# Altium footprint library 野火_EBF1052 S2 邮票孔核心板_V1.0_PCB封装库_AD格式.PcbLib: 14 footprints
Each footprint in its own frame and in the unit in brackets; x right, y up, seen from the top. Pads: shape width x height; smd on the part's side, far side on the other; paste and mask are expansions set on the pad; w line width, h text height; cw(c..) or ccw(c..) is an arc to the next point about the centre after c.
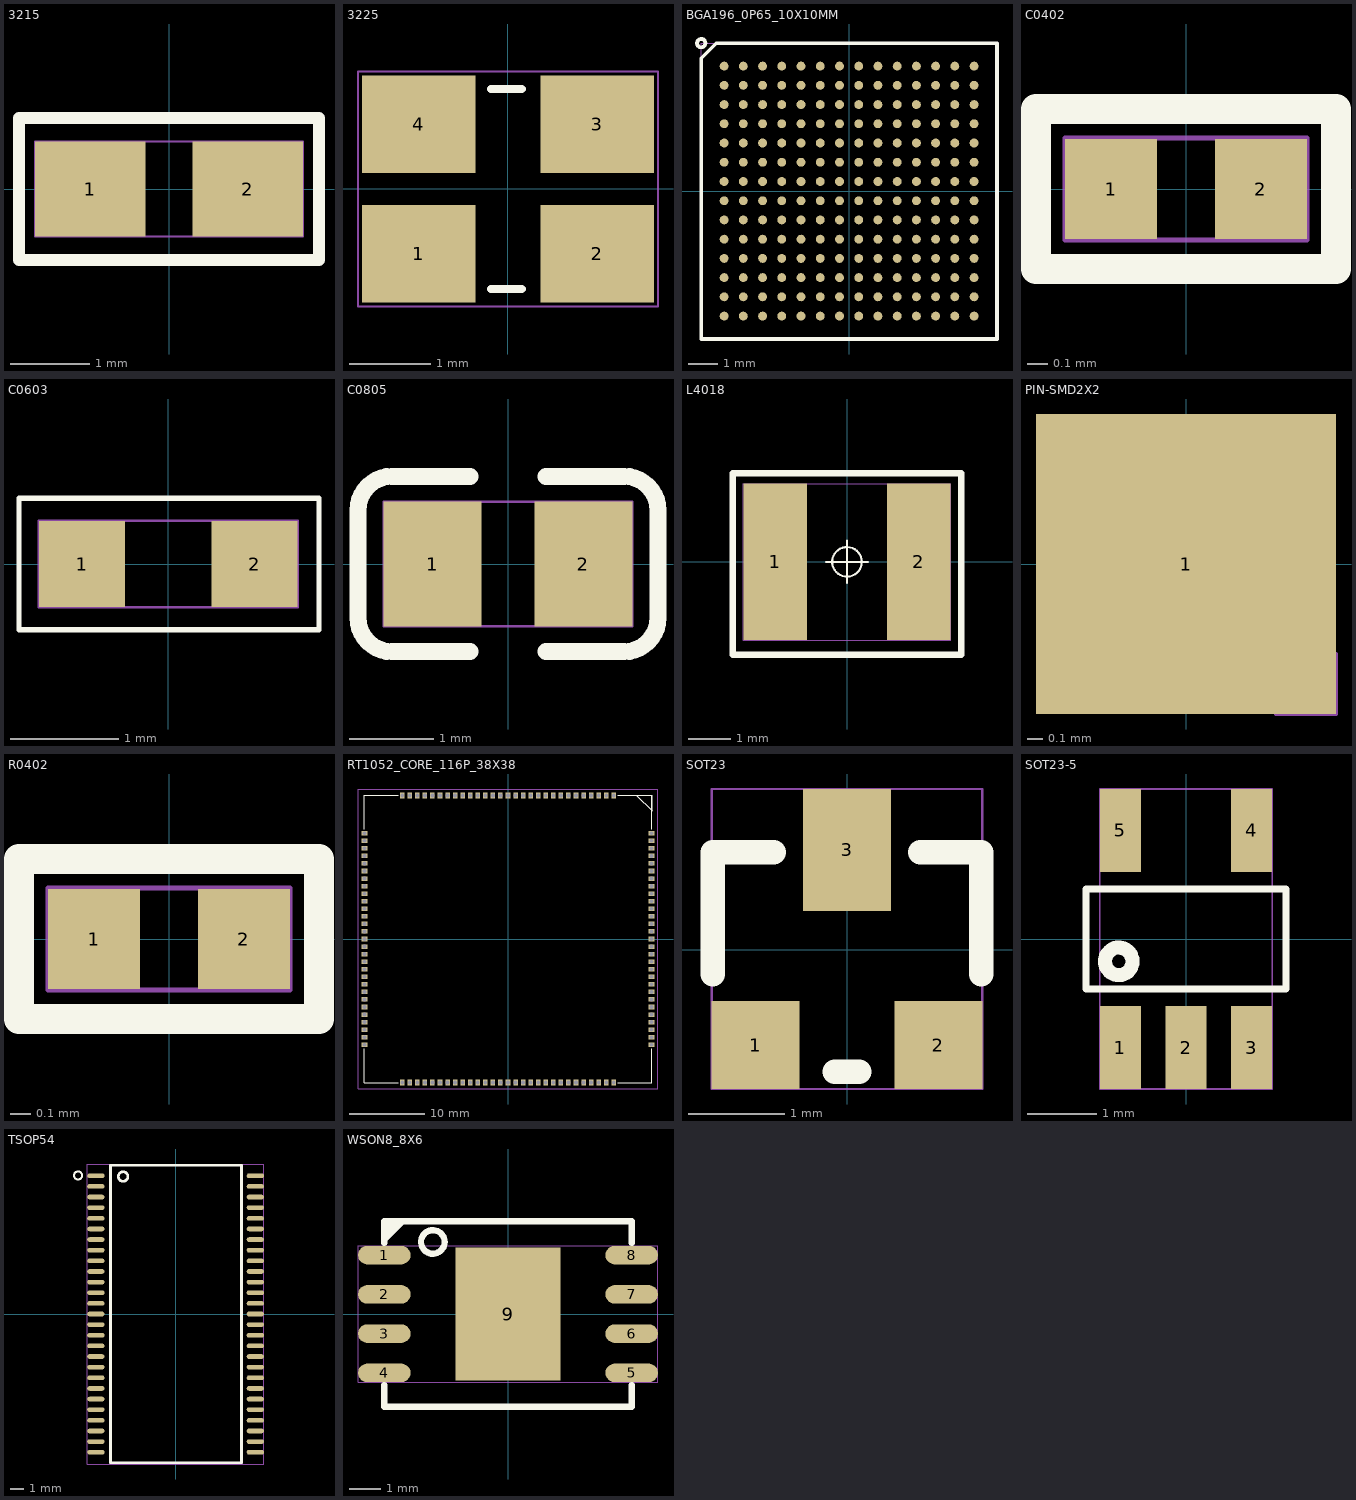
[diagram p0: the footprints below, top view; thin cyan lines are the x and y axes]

## 3215 [mm]
pads (2):
  rect 1.4x1.2 smd mask+0.05: 1(-1,0) 2(1,0)
Top Overlay:
  lines w0.15: -1.9,-0.9 1.9,-0.9 1.9,0.9 -1.9,0.9 -1.9,-0.9
Top Assembly:
  text "Y2" at -0.989,-0.635 h1.27
Mechanical 16:
  lines w0.025: -1.7,-0.6 -1.7,0.6 1.7,0.6 1.7,-0.6 -1.7,-0.6

## 3225 [mil]
pads (4):
  rect 55.12x47.24 smd mask+1.97: 1(-43.3,-31.5) 2(43.31,-31.5) 3(43.31,31.49) 4(-43.3,31.49)
Top Overlay:
  lines w3.94: -8.3,-48.51 6.7,-48.51 ; -8.3,48.51 6.7,48.51
Top Assembly:
  text "Y1" at 28.21,25 h50
Mechanical 16:
  lines w1: -72.83,-57.09 72.84,-57.09 72.84,57.08 -72.83,57.08 -72.83,-57.09

## BGA196_0P65_10X10MM [mm]
pads (196):
  round 0.3 smd mask+0.05: A1(-4.225,4.225) A2(-3.575,4.225) A3(-2.925,4.225) A4(-2.275,4.225) A5(-1.625,4.225) A6(-0.975,4.225) A7(-0.325,4.225) A8(0.325,4.225) A9(0.975,4.225) A10(1.625,4.225) A11(2.275,4.225) A12(2.925,4.225) A13(3.575,4.225) A14(4.225,4.225) B1(-4.225,3.575) B2(-3.575,3.575) B3(-2.925,3.575) B4(-2.275,3.575) B5(-1.625,3.575) B6(-0.975,3.575) B7(-0.325,3.575) B8(0.325,3.575) B9(0.975,3.575) B10(1.625,3.575) B11(2.275,3.575) B12(2.925,3.575) B13(3.575,3.575) B14(4.225,3.575) C1(-4.225,2.925) C2(-3.575,2.925) C3(-2.925,2.925) C4(-2.275,2.925) C5(-1.625,2.925) C6(-0.975,2.925) C7(-0.325,2.925) C8(0.325,2.925) C9(0.975,2.925) C10(1.625,2.925) C11(2.275,2.925) C12(2.925,2.925) C13(3.575,2.925) C14(4.225,2.925) D1(-4.225,2.275) D2(-3.575,2.275) D3(-2.925,2.275) D4(-2.275,2.275) D5(-1.625,2.275) D6(-0.975,2.275) D7(-0.325,2.275) D8(0.325,2.275) D9(0.975,2.275) D10(1.625,2.275) D11(2.275,2.275) D12(2.925,2.275) D13(3.575,2.275) D14(4.225,2.275) E1(-4.225,1.625) E2(-3.575,1.625) E3(-2.925,1.625) E4(-2.275,1.625) E5(-1.625,1.625) E6(-0.975,1.625) E7(-0.325,1.625) E8(0.325,1.625) E9(0.975,1.625) E10(1.625,1.625) E11(2.275,1.625) E12(2.925,1.625) E13(3.575,1.625) E14(4.225,1.625) F1(-4.225,0.975) F2(-3.575,0.975) F3(-2.925,0.975) F4(-2.275,0.975) F5(-1.625,0.975) F6(-0.975,0.975) F7(-0.325,0.975) F8(0.325,0.975) F9(0.975,0.975) F10(1.625,0.975) F11(2.275,0.975) F12(2.925,0.975) F13(3.575,0.975) F14(4.225,0.975) G1(-4.225,0.325) G2(-3.575,0.325) G3(-2.925,0.325) G4(-2.275,0.325) G5(-1.625,0.325) G6(-0.975,0.325) G7(-0.325,0.325) G8(0.325,0.325) G9(0.975,0.325) G10(1.625,0.325) G11(2.275,0.325) G12(2.925,0.325) G13(3.575,0.325) G14(4.225,0.325) H1(-4.225,-0.325) H2(-3.575,-0.325) H3(-2.925,-0.325) H4(-2.275,-0.325) H5(-1.625,-0.325) H6(-0.975,-0.325) H7(-0.325,-0.325) H8(0.325,-0.325) H9(0.975,-0.325) H10(1.625,-0.325) H11(2.275,-0.325) H12(2.925,-0.325) H13(3.575,-0.325) H14(4.225,-0.325) J1(-4.225,-0.975) J2(-3.575,-0.975) J3(-2.925,-0.975) J4(-2.275,-0.975) J5(-1.625,-0.975) J6(-0.975,-0.975) J7(-0.325,-0.975) J8(0.325,-0.975) J9(0.975,-0.975) J10(1.625,-0.975) J11(2.275,-0.975) J12(2.925,-0.975) J13(3.575,-0.975) J14(4.225,-0.975) K1(-4.225,-1.625) K2(-3.575,-1.625) K3(-2.925,-1.625) K4(-2.275,-1.625) K5(-1.625,-1.625) K6(-0.975,-1.625) K7(-0.325,-1.625) K8(0.325,-1.625) K9(0.975,-1.625) K10(1.625,-1.625) K11(2.275,-1.625) K12(2.925,-1.625) K13(3.575,-1.625) K14(4.225,-1.625) L1(-4.225,-2.275) L2(-3.575,-2.275) L3(-2.925,-2.275) L4(-2.275,-2.275) L5(-1.625,-2.275) L6(-0.975,-2.275) L7(-0.325,-2.275) L8(0.325,-2.275) L9(0.975,-2.275) L10(1.625,-2.275) L11(2.275,-2.275) L12(2.925,-2.275) L13(3.575,-2.275) L14(4.225,-2.275) M1(-4.225,-2.925) M2(-3.575,-2.925) M3(-2.925,-2.925) M4(-2.275,-2.925) M5(-1.625,-2.925) M6(-0.975,-2.925) M7(-0.325,-2.925) M8(0.325,-2.925) M9(0.975,-2.925) M10(1.625,-2.925) M11(2.275,-2.925) M12(2.925,-2.925) M13(3.575,-2.925) M14(4.225,-2.925) N1(-4.225,-3.575) N2(-3.575,-3.575) N3(-2.925,-3.575) N4(-2.275,-3.575) N5(-1.625,-3.575) N6(-0.975,-3.575) N7(-0.325,-3.575) N8(0.325,-3.575) N9(0.975,-3.575) N10(1.625,-3.575) N11(2.275,-3.575) N12(2.925,-3.575) N13(3.575,-3.575) N14(4.225,-3.575) P1(-4.225,-4.225) P2(-3.575,-4.225) P3(-2.925,-4.225) P4(-2.275,-4.225) P5(-1.625,-4.225) P6(-0.975,-4.225) P7(-0.325,-4.225) P8(0.325,-4.225) P9(0.975,-4.225) P10(1.625,-4.225) P11(2.275,-4.225) P12(2.925,-4.225) P13(3.575,-4.225) P14(4.225,-4.225)
Top Overlay:
  circle w0.127: c-5,5 r0.142
  lines w0.127: -5,-5 -5,4.492 ; -5,-5 5,-5 ; -5,-5 -5,4.492 ; -5,-5 5,-5 ; -5,4.492 -4.492,5 ; -5,4.492 -4.492,5 ; -4.492,5 5,5 ; -4.492,5 5,5 ; 5,-5 5,5 ; 5,-5 5,5
Top Assembly:
  text "U3" at -1.022,-0.635 h1.27
Mechanical 16:
  lines w0.025: -5,-5 5,-5 5,5 -5,5 -5,-5

## C0402 [mm]
pads (2):
  rect 0.46x0.5 smd mask+0.05: 1(-0.375,0) 2(0.375,0)
Top Overlay:
  lines w0.15: -0.75,-0.4 -0.75,0.4 0.75,0.4 0.75,-0.4 -0.75,-0.4
Top Assembly:
  text "C89" at 1.59,0.635 h1.27
Mechanical 16:
  lines w0.025: -0.605,-0.255 0.605,-0.255 0.605,0.255 -0.605,0.255 -0.605,-0.255

## C0603 [mil]
pads (2):
  rect 31.5x31.5 smd mask+1.97: 1(-31.5,0) 2(31.49,0)
Top Overlay:
  lines w2: -54.5,-24 55,-24 55,24 -54.5,24 -54.5,-24
Top Assembly:
  text "C92" at 63.8,25 h50
Mechanical 16:
  lines w1: -47.25,-15.75 47.24,-15.75 47.24,15.75 -47.25,15.75 -47.25,-15.75

## C0805 [mm]
pads (2):
  rect 1.16x1.47 smd mask+0.05: 1(-0.89,0) 2(0.89,0)
Top Overlay:
  lines w0.2: -0.45,-1.035 -1.37,-1.035 cw(c-1.37,-0.635) -1.77,-0.635 -1.77,0.635 cw(c-1.37,0.635) -1.37,1.035 -0.45,1.035 ; 0.45,-1.035 1.37,-1.035 ccw(c1.37,-0.635) 1.77,-0.635 1.77,0.635 ccw(c1.37,0.635) 1.37,1.035 0.45,1.035
Top Assembly:
  text "C44" at -1.651,-0.635 h1.27
Mechanical 16:
  lines w0.025: -1.47,-0.735 1.47,-0.735 1.47,0.735 -1.47,0.735 -1.47,-0.735

## L4018 [mm]
height 5.283
pads (2):
  rect 1.5x3.7 smd mask+0.05: 1(-1.7,0) 2(1.7,0)
Top Overlay:
  circle w0.05: c0,0 r0.35
  lines w0.05: -0.5,0 0.5,0 ; 0,-0.5 0,0.5
  lines w0.152: -2.7,-2.2 -2.7,2.1 2.7,2.1 2.7,-2.2 -2.7,-2.2
Top Assembly:
  text "L2" at -0.856,-0.635 h1.27
Mechanical 16:
  lines w0.025: -2.45,-1.85 2.45,-1.85 2.45,1.85 -2.45,1.85 -2.45,-1.85

## PIN-SMD2X2 [mm]
pads (1):
  rect 2x2 smd mask+0.05: 1(0,0)
Top Assembly:
  text "J4" at -0.919,-0.635 h1.27
Mechanical 16:
  lines w0.025: 0.6,-1 0.6,-0.6 1,-0.6 1,-1 0.6,-1

## R0402 [mm]
pads (2):
  rect 0.46x0.5 smd mask+0.05: 1(-0.375,0) 2(0.375,0)
Top Overlay:
  lines w0.15: -0.75,-0.4 -0.75,0.4 0.75,0.4 0.75,-0.4 -0.75,-0.4
Top Assembly:
  text "R94" at -1.584,-0.635 h1.27
Mechanical 16:
  lines w0.025: -0.605,-0.255 0.605,-0.255 0.605,0.255 -0.605,0.255 -0.605,-0.255

## RT1052_CORE_116P_38X38 [mil]
pads (116):
  rect 23.62x31.5 / inner rect 23.62x31.5 / far side rect 23.62x78.74 hole 19.69 mask+1.97: 1(551.18,748.03) 2(511.81,748.03) 3(472.44,748.03) 4(433.07,748.03) 5(393.7,748.03) 6(354.33,748.03) 7(314.96,748.03) 8(275.59,748.03) 9(236.22,748.03) 10(196.85,748.03) 11(157.48,748.03) 12(118.11,748.03) 13(78.74,748.03) 14(39.37,748.03) 15(0,748.03) 16(-39.37,748.03) 17(-78.74,748.03) 18(-118.11,748.03) 19(-157.48,748.03) 20(-196.85,748.03) 21(-236.22,748.03) 22(-275.59,748.03) 23(-314.96,748.03) 24(-354.33,748.03) 25(-393.7,748.03) 26(-433.07,748.03) 27(-472.44,748.03) 28(-511.81,748.03) 29(-551.18,748.03) 59(-551.18,-748.03) 60(-511.81,-748.03) 61(-472.44,-748.03) 62(-433.07,-748.03) 63(-393.7,-748.03) 64(-354.33,-748.03) 65(-314.96,-748.03) 66(-275.59,-748.03) 67(-236.22,-748.03) 68(-196.85,-748.03) 69(-157.48,-748.03) 70(-118.11,-748.03) 71(-78.74,-748.03) 72(-39.37,-748.03) 73(0,-748.03) 74(39.37,-748.03) 75(78.74,-748.03) 76(118.11,-748.03) 77(157.48,-748.03) 78(196.85,-748.03) 79(236.22,-748.03) 80(275.59,-748.03) 81(314.96,-748.03) 82(354.33,-748.03) 83(393.7,-748.03) 84(433.07,-748.03) 85(472.44,-748.03) 86(511.81,-748.03) 87(551.18,-748.03)
  rect 31.5x23.62 / inner rect 31.5x23.62 / far side rect 78.74x23.62 hole 19.69 mask+1.97: 30(-748.03,551.18) 31(-748.03,511.81) 32(-748.03,472.44) 33(-748.03,433.07) 34(-748.03,393.7) 35(-748.03,354.33) 36(-748.03,314.96) 37(-748.03,275.59) 38(-748.03,236.22) 39(-748.03,196.85) 40(-748.03,157.48) 41(-748.03,118.11) 42(-748.03,78.74) 43(-748.03,39.37) 44(-748.03,0) 45(-748.03,-39.37) 46(-748.03,-78.74) 47(-748.03,-118.11) 48(-748.03,-157.48) 49(-748.03,-196.85) 50(-748.03,-236.22) 51(-748.03,-275.59) 52(-748.03,-314.96) 53(-748.03,-354.33) 54(-748.03,-393.7) 55(-748.03,-433.07) 56(-748.03,-472.44) 57(-748.03,-511.81) 58(-748.03,-551.18) 88(748.03,-551.18) 89(748.03,-511.81) 90(748.03,-472.44) 91(748.03,-433.07) 92(748.03,-393.7) 93(748.03,-354.33) 94(748.03,-314.96) 95(748.03,-275.59) 96(748.03,-236.22) 97(748.03,-196.85) 98(748.03,-157.48) 99(748.03,-118.11) 100(748.03,-78.74) 101(748.03,-39.37) 102(748.03,0) 103(748.03,39.37) 104(748.03,78.74) 105(748.03,118.11) 106(748.03,157.48) 107(748.03,196.85) 108(748.03,236.22) 109(748.03,275.59) 110(748.03,314.96) 111(748.03,354.33) 112(748.03,393.7) 113(748.03,433.07) 114(748.03,472.44) 115(748.03,511.81) 116(748.03,551.18)
Top Overlay:
  lines w1: 668.54,748.78 750.31,667.01 750.31,748.78 668.54,748.78
  lines w6: -748.03,-748.23 -570.87,-748.03 -748.03,-748.23 ; -748.03,-748.23 -748.03,-570.87 -748.03,-748.23 ; -748.03,748.23 -748.03,570.87 -748.03,748.23 ; -748.03,748.23 -570.87,748.03 -748.03,748.23 ; 748.03,-748.23 570.87,-748.03 748.03,-748.23 ; 748.03,-748.23 748.03,-570.87 748.03,-748.23 ; 570.87,748.03 748.03,748.03 570.87,748.03 ; 748.03,570.87 748.03,748.23 748.03,570.87
Top Assembly:
  text "U23" at -62.49,-25 h50
Mechanical 16:
  lines w1: -781.5,-781.5 781.5,-781.5 781.5,781.5 -781.5,781.5 -781.5,-781.5

## SOT23 [mil]
pads (3):
  rect 36x36 smd mask+1.97: 1(-37.5,-39) 2(37.5,-39)
  rect 36x50 smd mask+1.97: 3(0,41)
Top Overlay:
  lines w10: -55,-10 -55,40 -30,40 ; -5,-50 5,-50 ; 30,40 55,40 55,-10
Top Assembly:
  text "Q1" at 30.83,27.38 h50
Mechanical 16:
  lines w1: -55.5,-57 55.5,-57 55.5,66 -55.5,66 -55.5,-57

## SOT23-5 [mm]
pads (5):
  rect 0.6x1.2 smd mask+0.05: 1(-0.95,-1.575) 2(0,-1.575) 3(0.95,-1.575) 4(0.95,1.575) 5(-0.95,1.575)
Top Overlay:
  circle w0.203: c-0.975,-0.325 r0.2
  lines w0.102: -1.45,-0.725 -1.45,0.475 -1.45,0.725 1.45,0.725 1.45,0.475 1.45,-0.725 -1.45,-0.725
Top Assembly:
  text "U7" at 1.022,0.635 h1.27
Mechanical 16:
  lines w0.025: -1.25,-2.175 1.25,-2.175 1.25,2.175 -1.25,2.175 -1.25,-2.175

## TSOP54 [mm]
pads (54):
  oval 1.3x0.35 smd mask+0.05: 1(-6,10.4) 2(-6,9.6) 3(-6,8.8) 4(-6,8) 5(-6,7.2) 6(-6,6.4) 7(-6,5.6) 8(-6,4.8) 9(-6,4) 10(-6,3.2) 11(-6,2.4) 12(-6,1.6) 13(-6,0.8) 14(-6,0) 15(-6,-0.8) 16(-6,-1.6) 17(-6,-2.4) 18(-6,-3.2) 19(-6,-4) 20(-6,-4.8) 21(-6,-5.6) 22(-6,-6.4) 23(-6,-7.2) 24(-6,-8) 25(-6,-8.8) 26(-6,-9.6) 27(-6,-10.4) 28(6,-10.4) 29(6,-9.6) 30(6,-8.8) 31(6,-8) 32(6,-7.2) 33(6,-6.4) 34(6,-5.6) 35(6,-4.8) 36(6,-4) 37(6,-3.2) 38(6,-2.4) 39(6,-1.6) 40(6,-0.8) 41(6,0) 42(6,0.8) 43(6,1.6) 44(6,2.4) 45(6,3.2) 46(6,4) 47(6,4.8) 48(6,5.6) 49(6,6.4) 50(6,7.2) 51(6,8) 52(6,8.8) 53(6,9.6) 54(6,10.4)
Top Overlay:
  circle w0.152: c-7.337,10.424 r0.305
  circle w0.2: c-3.95,10.34 r0.361
  lines w0.2: -4.9,-11.2 -4.9,11.2 ; -4.9,-11.2 4.96,-11.2 ; -4.9,-11.2 -4.9,11.2 ; -4.9,-11.2 4.96,-11.2 ; -4.9,11.2 4.96,11.2 ; -4.9,11.2 4.96,11.2 ; 4.96,-11.2 4.96,11.2 ; 4.96,-11.2 4.96,11.2
Top Assembly:
  text "U6" at -0.992,-0.635 h1.27
Mechanical 16:
  lines w0.025: -6.65,-11.286 -6.65,11.286 6.65,11.286 6.65,-11.286 -6.65,-11.286

## WSON8_8X6 [mm]
pads (9):
  oval 1.7x0.6 smd mask+0.05: 1(-4,1.905) 2(-4,0.635) 3(-4,-0.635) 4(-4,-1.905) 5(4,-1.905) 6(4,-0.635) 7(4,0.635) 8(4,1.905)
  rect 3.4x4.3 smd mask+0.05: 9(0,0)
Top Overlay:
  circle w0.203: c-2.43,2.33 r0.381
  lines w0.2: -4,-2.3 -4,-3 4,-3 4,-2.3 ; -4,2.3 -4,3 4,3 4,2.3 ; -4,2.4 -3.4,3 ; -4,2.6 -3.6,3 ; -4,2.8 -3.8,3
Top Paste:
  lines w0.025: -1.3,-1.3 -1.3,-0.2 -0.3,-0.2 -0.3,-1.3 -1.3,-1.3 ; -1.3,0.2 -1.3,1.3 -0.3,1.3 -0.3,0.2 -1.3,0.2 ; 0.3,-1.3 0.3,-0.2 1.3,-0.2 1.3,-1.3 0.3,-1.3 ; 0.3,0.2 0.3,1.3 1.3,1.3 1.3,0.2 0.3,0.2
Top Assembly:
  text "U8" at 1.022,0.635 h1.27
Mechanical 16:
  lines w0.025: -4.85,-2.205 4.85,-2.205 4.85,2.205 -4.85,2.205 -4.85,-2.205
